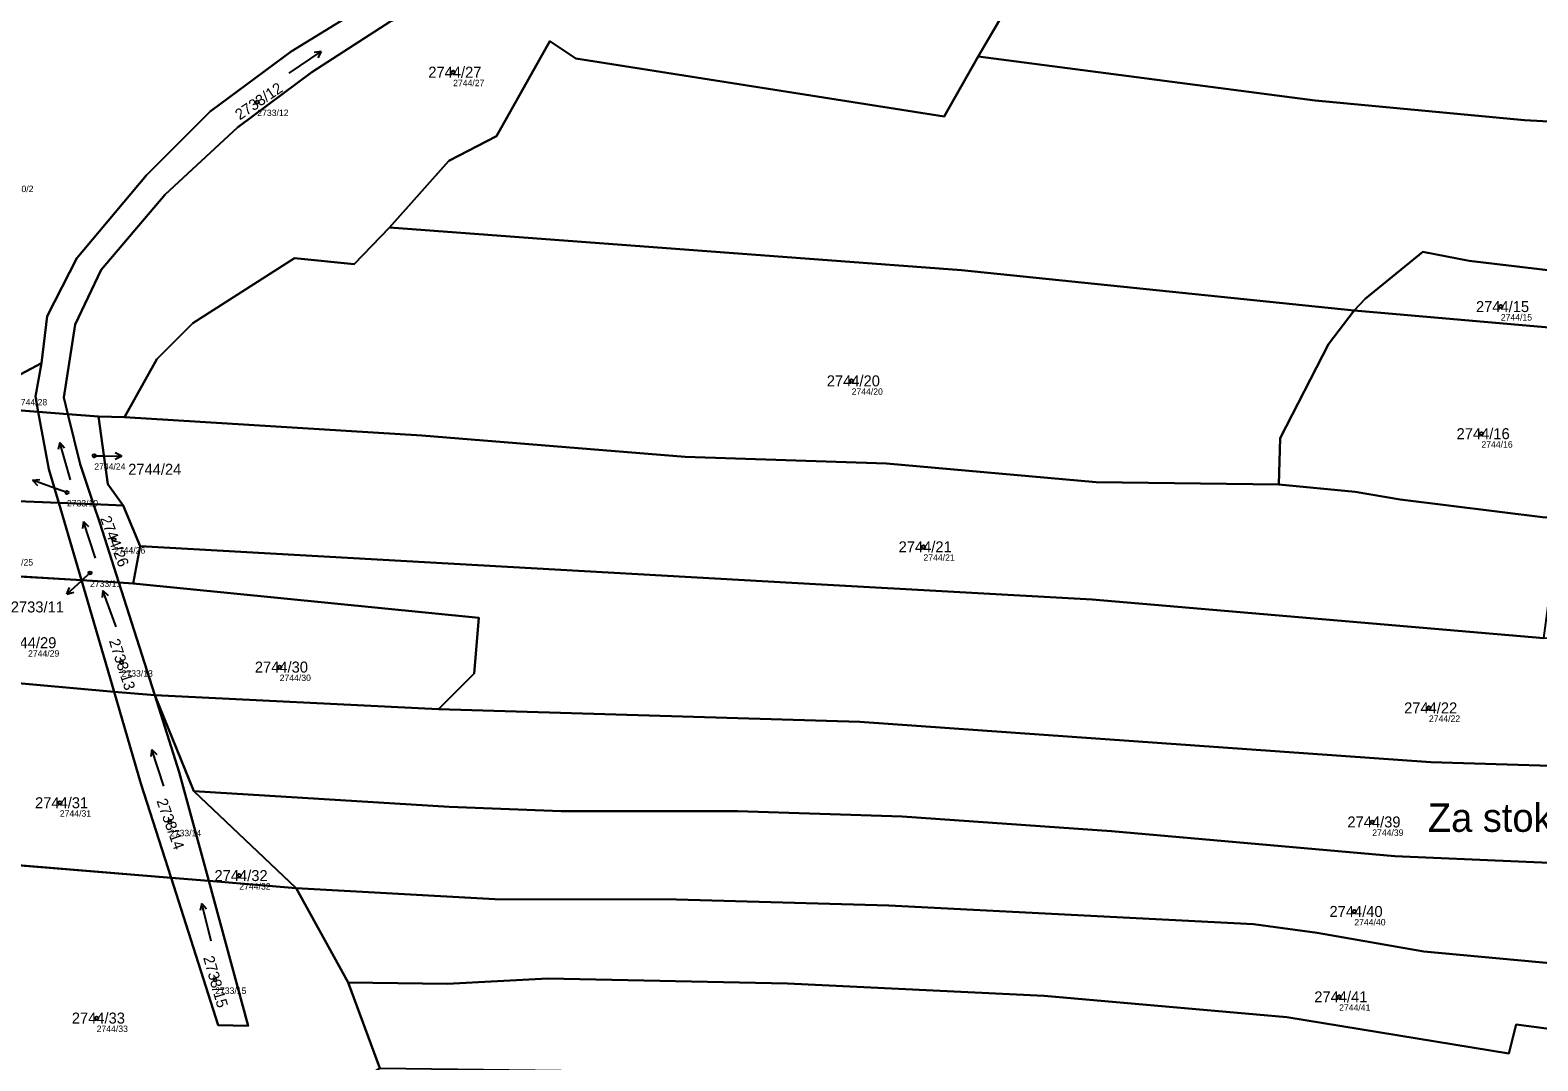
# Model space of a CAD drawing. Extents: x -739214 to -733252, y -1147612 to -1142842.
# Drawn here: x -737932.2 to -737699, y -1144633.5 to -1144474 of the extents above; entities that cross this region are included whole.
import ezdxf

# ---------------------------------------------------------------- set-up
doc = ezdxf.new("R2010")
doc.units = 0
for name, color, linetype in [('Definiční body', 7, 'Continuous'), ('Hranice parcel', 7, 'Continuous'), ('Parcelní čísla', 7, 'Continuous'), ('Polygon parcely', 7, 'Continuous'), ('Pop  PČ popisy', 7, 'Continuous'), ('Značky kultur', 7, 'Continuous')]:
    doc.layers.add(name, color=color, linetype=linetype)

msp = doc.modelspace()

# ---------------------------------------------------------------- linework, layer by layer
at = {"layer": 'Definiční body'}
for centre in [(-737866.8, -1144480.52), (-737897.09, -1144485.14), (-737704.74, -1144516.78), (-737805.16, -1144528.27), (-737707.74, -1144536.44), (-737922.31, -1144539.86), (-737926.54, -1144545.54), (-737919.25, -1144552.83), (-737794.05, -1144553.95), (-737922.97, -1144557.99), (-737918.08, -1144571.87), (-737893.63, -1144572.55), (-737715.86, -1144578.87), (-737927.63, -1144593.54), (-737910.61, -1144596.57), (-737724.63, -1144596.51), (-737899.87, -1144604.81), (-737727.4, -1144610.36), (-737903.61, -1144620.96), (-737729.75, -1144623.57), (-737921.94, -1144626.85)]:
    msp.add_circle(centre, 0.25, dxfattribs=at)
at = {"layer": 'Hranice parcel'}
for p, q in [((-737773.14, -1144456.81), (-737785.6, -1144478.09)), ((-737727.43, -1144517.4), (-737686.65, -1144520.92)), ((-737942.95, -1144532.13), (-737930.48, -1144525.51)), ((-737930.97, -1144533.06), (-737942.95, -1144532.13)), ((-737926.39, -1144533.41), (-737930.97, -1144533.06)), ((-737921.63, -1144533.78), (-737926.39, -1144533.41)), ((-737917.65, -1144533.91), (-737921.63, -1144533.78)), ((-737953.32, -1144546.12), (-737927.79, -1144547.13)), ((-737927.79, -1144547.13), (-737922.41, -1144547.35)), ((-737927.79, -1144547.13), (-737924.28, -1144559.12)), ((-737922.41, -1144547.35), (-737917.82, -1144547.53)), ((-737917.82, -1144547.53), (-737915.23, -1144553.85)), ((-737915.23, -1144553.85), (-737916.31, -1144559.61)), ((-737948.93, -1144557.6), (-737924.28, -1144559.12)), ((-737924.28, -1144559.12), (-737918.5, -1144559.48)), ((-737924.28, -1144559.12), (-737919.24, -1144576.36)), ((-737912.96, -1144576.92), (-737918.5, -1144559.48)), ((-737918.5, -1144559.48), (-737916.31, -1144559.61)), ((-737943.32, -1144574.2), (-737919.24, -1144576.36)), ((-737919.24, -1144576.36), (-737912.96, -1144576.92)), ((-737912.96, -1144576.92), (-737869.05, -1144579.05)), ((-737906.92, -1144591.77), (-737912.96, -1144576.92)), ((-737891.06, -1144606.75), (-737906.92, -1144591.77)), ((-737942.86, -1144602.48), (-737910.42, -1144605.15)), ((-737910.42, -1144605.15), (-737904.6, -1144605.63)), ((-737904.6, -1144605.63), (-737891.06, -1144606.75)), ((-737883.04, -1144621.37), (-737891.06, -1144606.75)), ((-737878.15, -1144634.59), (-737883.04, -1144621.37))]:
    msp.add_line(p, q, dxfattribs=at)
for points in [[(-737926.39, -1144533.41), (-737927.01, -1144530.86), (-737925.24, -1144519.57), (-737921.26, -1144511.11), (-737911.32, -1144499.46), (-737900.13, -1144489.08), (-737888.65, -1144480.5), (-737876.41, -1144472.62), (-737867.2, -1144468.83), (-737814.62, -1144454.1)], [(-737868.17, -1144464.26), (-737877.57, -1144468.52), (-737891.83, -1144477.32), (-737904.38, -1144486.62), (-737914.24, -1144496.47), (-737925.02, -1144509.31), (-737929.6, -1144518.25), (-737930.48, -1144525.51)], [(-737785.6, -1144478.09), (-737790.83, -1144487.35), (-737847.8, -1144478.4), (-737851.84, -1144475.71), (-737860.11, -1144490.42), (-737867.48, -1144494.24), (-737876.62, -1144504.52)], [(-737785.6, -1144478.09), (-737733.45, -1144484.87), (-737701.09, -1144487.96), (-737676.5, -1144489.26), (-737627.87, -1144492.95), (-737616.17, -1144494.42), (-737600.37, -1144496.74), (-737576.07, -1144501.23), (-737531.09, -1144511.5)], [(-737876.62, -1144504.52), (-737882.12, -1144510.23), (-737891.36, -1144509.31), (-737907.07, -1144519.34), (-737912.62, -1144524.89), (-737917.65, -1144533.91)], [(-737876.62, -1144504.52), (-737788.18, -1144511.16), (-737727.43, -1144517.4)], [(-737686.65, -1144520.92), (-737690.94, -1144511.91), (-737709.62, -1144509.71), (-737716.8, -1144508.31), (-737725.74, -1144515.57), (-737727.43, -1144517.4)], [(-737727.43, -1144517.4), (-737731.38, -1144522.61), (-737738.86, -1144537.12), (-737739.08, -1144544.3)], [(-737930.48, -1144525.51), (-737931.41, -1144530.71), (-737930.97, -1144533.06)], [(-737930.97, -1144533.06), (-737929.31, -1144541.92), (-737927.79, -1144547.13)], [(-737922.41, -1144547.35), (-737924.51, -1144541.16), (-737926.39, -1144533.41)], [(-737921.63, -1144533.78), (-737920.23, -1144544.27), (-737917.82, -1144547.53)], [(-737917.65, -1144533.91), (-737871.65, -1144536.72), (-737830.89, -1144540), (-737799.75, -1144541.03), (-737767.34, -1144543.94), (-737739.08, -1144544.3)], [(-737739.08, -1144544.3), (-737727.27, -1144545.46), (-737720.31, -1144546.63), (-737697.89, -1144549.41), (-737695, -1144549.36)], [(-737918.5, -1144559.48), (-737921.44, -1144550.22), (-737922.41, -1144547.35)], [(-737915.23, -1144553.85), (-737809.84, -1144559.77), (-737767.94, -1144562.09), (-737698.06, -1144568.08)], [(-737916.31, -1144559.61), (-737862.81, -1144564.94), (-737863.56, -1144573.56), (-737869.05, -1144579.05)], [(-737919.24, -1144576.36), (-737915.09, -1144590.56), (-737910.42, -1144605.15)], [(-737904.6, -1144605.63), (-737909.18, -1144588.8), (-737912.96, -1144576.92)], [(-737869.05, -1144579.05), (-737803.9, -1144581.02), (-737715.55, -1144587.26), (-737685.17, -1144588.21), (-737656.28, -1144590.45), (-737617.07, -1144596.37), (-737591.52, -1144603.26), (-737561.95, -1144613.5)], [(-737906.92, -1144591.77), (-737867.39, -1144594.16), (-737850.07, -1144594.84), (-737822.81, -1144594.85), (-737797.36, -1144595.68), (-737764.97, -1144597.96), (-737721.14, -1144601.78), (-737682.9, -1144603.46), (-737658.14, -1144605.97), (-737622.11, -1144611.46), (-737598.66, -1144617.19), (-737580.09, -1144623.04), (-737568.5, -1144628.61)], [(-737910.42, -1144605.15), (-737903.13, -1144627.93), (-737898.51, -1144628.03), (-737904.6, -1144605.63)], [(-737891.06, -1144606.75), (-737860.35, -1144608.46), (-737832.24, -1144608.5), (-737799.41, -1144609.43), (-737743.02, -1144612.33), (-737733.13, -1144613.67), (-737716.64, -1144616.57), (-737696.03, -1144618.45), (-737694.77, -1144614.8), (-737657.82, -1144619.67), (-737629.39, -1144624.64), (-737616.03, -1144627.71), (-737585.66, -1144636.92), (-737573.23, -1144641.35)], [(-737883.04, -1144621.37), (-737867.73, -1144621.57), (-737852.15, -1144620.71), (-737815.08, -1144621.5), (-737775.39, -1144623.43), (-737737.84, -1144626.71), (-737703.5, -1144632.35), (-737702.39, -1144627.85), (-737672.66, -1144631.78), (-737651.8, -1144635.91), (-737632.6, -1144639.06), (-737609.23, -1144646.15), (-737582.22, -1144655.83)]]:
    msp.add_lwpolyline(points, dxfattribs=at)
at = {"layer": 'Polygon parcely'}
for points in [[(-737676.5, -1144489.26), (-737627.87, -1144492.95), (-737616.17, -1144494.42), (-737600.37, -1144496.74), (-737576.07, -1144501.23), (-737531.09, -1144511.5), (-737529.44, -1144511.78), (-737526.15, -1144491.59), (-737527.8, -1144458.01), (-737551.39, -1144455.57), (-737569.83, -1144452.11), (-737583.62, -1144450.77), (-737650.15, -1144446.91), (-737705.41, -1144442.38), (-737711.09, -1144441.92), (-737719.38, -1144441.24), (-737747.06, -1144439.73), (-737762.92, -1144440.22), (-737769.4, -1144441.94), (-737768.36, -1144448.37), (-737773.14, -1144456.81), (-737785.6, -1144478.09), (-737733.45, -1144484.87), (-737701.09, -1144487.96)], [(-737931.41, -1144530.71), (-737930.97, -1144533.06), (-737926.39, -1144533.41), (-737927.01, -1144530.86), (-737925.24, -1144519.57), (-737921.26, -1144511.11), (-737911.32, -1144499.46), (-737900.13, -1144489.08), (-737888.65, -1144480.5), (-737876.41, -1144472.62), (-737867.2, -1144468.83), (-737814.62, -1144454.1), (-737835.54, -1144454.6), (-737868.17, -1144464.26), (-737877.57, -1144468.52), (-737891.83, -1144477.32), (-737904.38, -1144486.62), (-737914.24, -1144496.47), (-737925.02, -1144509.31), (-737929.6, -1144518.25), (-737930.48, -1144525.51)], [(-737955.11, -1144459.11), (-737955.01, -1144470.75), (-737954.9, -1144484.25), (-737955.35, -1144491.07), (-737956.06, -1144501.75), (-737958.01, -1144530.96), (-737942.95, -1144532.13), (-737930.48, -1144525.51), (-737929.6, -1144518.25), (-737925.02, -1144509.31), (-737914.24, -1144496.47), (-737904.38, -1144486.62), (-737891.83, -1144477.32), (-737877.57, -1144468.52), (-737868.17, -1144464.26), (-737934.96, -1144460.74)], [(-737830.89, -1144540), (-737799.75, -1144541.03), (-737767.34, -1144543.94), (-737739.08, -1144544.3), (-737738.86, -1144537.12), (-737731.38, -1144522.61), (-737727.43, -1144517.4), (-737788.18, -1144511.16), (-737876.62, -1144504.52), (-737882.12, -1144510.23), (-737891.36, -1144509.31), (-737907.07, -1144519.34), (-737912.62, -1144524.89), (-737917.65, -1144533.91), (-737871.65, -1144536.72)], [(-737716.8, -1144508.31), (-737725.74, -1144515.57), (-737727.43, -1144517.4), (-737686.65, -1144520.92), (-737690.94, -1144511.91), (-737709.62, -1144509.71)], [(-737738.86, -1144537.12), (-737739.08, -1144544.3), (-737727.27, -1144545.46), (-737720.31, -1144546.63), (-737697.89, -1144549.41), (-737695, -1144549.36), (-737672.64, -1144549.91), (-737686.65, -1144520.92), (-737727.43, -1144517.4), (-737731.38, -1144522.61)], [(-737930.97, -1144533.06), (-737931.41, -1144530.71), (-737930.48, -1144525.51), (-737942.95, -1144532.13)], [(-737930.97, -1144533.06), (-737942.95, -1144532.13), (-737956.02, -1144539.07), (-737953.32, -1144546.12), (-737927.79, -1144547.13), (-737929.31, -1144541.92)], [(-737927.79, -1144547.13), (-737922.41, -1144547.35), (-737924.51, -1144541.16), (-737926.39, -1144533.41), (-737930.97, -1144533.06), (-737929.31, -1144541.92)], [(-737917.82, -1144547.53), (-737920.23, -1144544.27), (-737921.63, -1144533.78), (-737926.39, -1144533.41), (-737924.51, -1144541.16), (-737922.41, -1144547.35)], [(-737920.23, -1144544.27), (-737917.82, -1144547.53), (-737915.23, -1144553.85), (-737809.84, -1144559.77), (-737767.94, -1144562.09), (-737698.06, -1144568.08), (-737697.18, -1144561.12), (-737695, -1144549.36), (-737697.89, -1144549.41), (-737720.31, -1144546.63), (-737727.27, -1144545.46), (-737739.08, -1144544.3), (-737767.34, -1144543.94), (-737799.75, -1144541.03), (-737830.89, -1144540), (-737871.65, -1144536.72), (-737917.65, -1144533.91), (-737921.63, -1144533.78)], [(-737948.93, -1144557.6), (-737924.28, -1144559.12), (-737927.79, -1144547.13), (-737953.32, -1144546.12)], [(-737918.5, -1144559.48), (-737921.44, -1144550.22), (-737922.41, -1144547.35), (-737927.79, -1144547.13), (-737924.28, -1144559.12)], [(-737916.31, -1144559.61), (-737915.23, -1144553.85), (-737917.82, -1144547.53), (-737922.41, -1144547.35), (-737921.44, -1144550.22), (-737918.5, -1144559.48)], [(-737656.28, -1144590.45), (-737617.07, -1144596.37), (-737591.52, -1144603.26), (-737561.95, -1144613.5), (-737555.62, -1144598.88), (-737581.61, -1144590.43), (-737616.17, -1144581.32), (-737646.17, -1144576.7), (-737670.78, -1144574.07), (-737677.25, -1144574.53), (-737692.27, -1144572.92), (-737694.4, -1144568.38), (-737698.06, -1144568.08), (-737767.94, -1144562.09), (-737809.84, -1144559.77), (-737915.23, -1144553.85), (-737916.31, -1144559.61), (-737862.81, -1144564.94), (-737863.56, -1144573.56), (-737869.05, -1144579.05), (-737803.9, -1144581.02), (-737715.55, -1144587.26), (-737685.17, -1144588.21)], [(-737944.37, -1144569.52), (-737943.32, -1144574.2), (-737919.24, -1144576.36), (-737924.28, -1144559.12), (-737948.93, -1144557.6)], [(-737912.96, -1144576.92), (-737918.5, -1144559.48), (-737924.28, -1144559.12), (-737919.24, -1144576.36)], [(-737869.05, -1144579.05), (-737863.56, -1144573.56), (-737862.81, -1144564.94), (-737916.31, -1144559.61), (-737918.5, -1144559.48), (-737912.96, -1144576.92)], [(-737910.42, -1144605.15), (-737915.09, -1144590.56), (-737919.24, -1144576.36), (-737943.32, -1144574.2), (-737940.96, -1144584.68), (-737942.86, -1144602.48)], [(-737904.6, -1144605.63), (-737909.18, -1144588.8), (-737912.96, -1144576.92), (-737919.24, -1144576.36), (-737915.09, -1144590.56), (-737910.42, -1144605.15)], [(-737891.06, -1144606.75), (-737906.92, -1144591.77), (-737912.96, -1144576.92), (-737909.18, -1144588.8), (-737904.6, -1144605.63)], [(-737598.66, -1144617.19), (-737580.09, -1144623.04), (-737568.5, -1144628.61), (-737561.95, -1144613.5), (-737591.52, -1144603.26), (-737617.07, -1144596.37), (-737656.28, -1144590.45), (-737685.17, -1144588.21), (-737715.55, -1144587.26), (-737803.9, -1144581.02), (-737869.05, -1144579.05), (-737912.96, -1144576.92), (-737906.92, -1144591.77), (-737867.39, -1144594.16), (-737850.07, -1144594.84), (-737822.81, -1144594.85), (-737797.36, -1144595.68), (-737764.97, -1144597.96), (-737721.14, -1144601.78), (-737682.9, -1144603.46), (-737658.14, -1144605.97), (-737622.11, -1144611.46)], [(-737883.04, -1144621.37), (-737891.06, -1144606.75), (-737904.6, -1144605.63), (-737898.51, -1144628.03), (-737903.13, -1144627.93), (-737910.42, -1144605.15), (-737942.86, -1144602.48), (-737947.13, -1144642.41), (-737936.59, -1144643.76), (-737914.72, -1144642.53), (-737901.54, -1144642.73), (-737892.69, -1144643.45), (-737878.15, -1144634.59)], [(-737910.42, -1144605.15), (-737903.13, -1144627.93), (-737898.51, -1144628.03), (-737904.6, -1144605.63)], [(-737637.35, -1144649.22), (-737604.53, -1144659.49), (-737591.13, -1144664.67), (-737582.22, -1144655.83), (-737609.23, -1144646.15), (-737632.6, -1144639.06), (-737651.8, -1144635.91), (-737672.66, -1144631.78), (-737702.39, -1144627.85), (-737703.5, -1144632.35), (-737737.84, -1144626.71), (-737775.39, -1144623.43), (-737815.08, -1144621.5), (-737852.15, -1144620.71), (-737867.73, -1144621.57), (-737883.04, -1144621.37), (-737878.15, -1144634.59), (-737806.05, -1144635.53), (-737772.78, -1144637.39), (-737734.45, -1144641.63), (-737704.83, -1144645.91), (-737703.81, -1144636.4), (-737667.6, -1144642.51)]]:
    msp.add_lwpolyline(points, close=True, dxfattribs=at)
for points in [[(-737876.41, -1144472.62), (-737888.65, -1144480.5), (-737900.13, -1144489.08), (-737911.32, -1144499.46), (-737921.26, -1144511.11), (-737925.24, -1144519.57), (-737927.01, -1144530.86), (-737926.39, -1144533.41), (-737921.63, -1144533.78), (-737917.65, -1144533.91), (-737912.62, -1144524.89), (-737907.07, -1144519.34), (-737891.36, -1144509.31), (-737882.12, -1144510.23), (-737876.62, -1144504.52), (-737867.48, -1144494.24), (-737860.11, -1144490.42), (-737851.84, -1144475.71), (-737847.8, -1144478.4), (-737790.83, -1144487.35), (-737785.6, -1144478.09), (-737773.14, -1144456.81)], [(-737676.5, -1144489.26), (-737701.09, -1144487.96), (-737733.45, -1144484.87), (-737785.6, -1144478.09), (-737790.83, -1144487.35), (-737847.8, -1144478.4), (-737851.84, -1144475.71), (-737860.11, -1144490.42), (-737867.48, -1144494.24), (-737876.62, -1144504.52), (-737788.18, -1144511.16), (-737727.43, -1144517.4), (-737725.74, -1144515.57), (-737716.8, -1144508.31), (-737709.62, -1144509.71), (-737690.94, -1144511.91)], [(-737682.9, -1144603.46), (-737721.14, -1144601.78), (-737764.97, -1144597.96), (-737797.36, -1144595.68), (-737822.81, -1144594.85), (-737850.07, -1144594.84), (-737867.39, -1144594.16), (-737906.92, -1144591.77), (-737891.06, -1144606.75), (-737860.35, -1144608.46), (-737832.24, -1144608.5), (-737799.41, -1144609.43), (-737743.02, -1144612.33), (-737733.13, -1144613.67), (-737716.64, -1144616.57), (-737696.03, -1144618.45)], [(-737696.03, -1144618.45), (-737716.64, -1144616.57), (-737733.13, -1144613.67), (-737743.02, -1144612.33), (-737799.41, -1144609.43), (-737832.24, -1144608.5), (-737860.35, -1144608.46), (-737891.06, -1144606.75), (-737883.04, -1144621.37), (-737867.73, -1144621.57), (-737852.15, -1144620.71), (-737815.08, -1144621.5), (-737775.39, -1144623.43), (-737737.84, -1144626.71), (-737703.5, -1144632.35), (-737702.39, -1144627.85), (-737672.66, -1144631.78)]]:
    msp.add_lwpolyline(points, dxfattribs=at)
at = {"layer": 'Pop  PČ popisy'}
for p, q in [((-737922.31, -1144539.86), (-737921.06, -1144539.89)), ((-737921.06, -1144539.89), (-737918.06, -1144539.94)), ((-737918.06, -1144539.94), (-737919.07, -1144540.43)), ((-737918.06, -1144539.94), (-737919.05, -1144539.42)), ((-737931.84, -1144543.63), (-737930.73, -1144543.51)), ((-737929.02, -1144544.66), (-737931.84, -1144543.63)), ((-737931.84, -1144543.63), (-737931.07, -1144544.45)), ((-737926.54, -1144545.54), (-737929.02, -1144544.66)), ((-737924.33, -1144559.24), (-737926.53, -1144561.29)), ((-737922.97, -1144557.99), (-737924.33, -1144559.24)), ((-737926.53, -1144561.29), (-737926.13, -1144560.24)), ((-737926.53, -1144561.29), (-737925.45, -1144560.97))]:
    msp.add_line(p, q, dxfattribs=at)
at = {"layer": 'Značky kultur'}
for p, q in [((-737892.18, -1144480.69), (-737887.2, -1144477.33)), ((-737887.2, -1144477.33), (-737888.29, -1144477.46)), ((-737887.2, -1144477.33), (-737887.73, -1144478.29)), ((-737927.65, -1144537.82), (-737927.87, -1144538.9)), ((-737926, -1144543.58), (-737927.65, -1144537.82)), ((-737927.65, -1144537.82), (-737926.9, -1144538.62)), ((-737923.97, -1144550.01), (-737924.15, -1144551.09)), ((-737922.12, -1144555.71), (-737923.97, -1144550.01)), ((-737923.97, -1144550.01), (-737923.2, -1144550.78)), ((-737920.97, -1144560.7), (-737921.11, -1144561.79)), ((-737918.92, -1144566.34), (-737920.97, -1144560.7)), ((-737920.97, -1144560.7), (-737920.17, -1144561.45)), ((-737913.39, -1144585.29), (-737913.57, -1144586.37)), ((-737911.54, -1144590.99), (-737913.39, -1144585.29)), ((-737913.39, -1144585.29), (-737912.61, -1144586.06)), ((-737905.69, -1144609.12), (-737905.94, -1144610.19)), ((-737904.24, -1144614.94), (-737905.69, -1144609.12)), ((-737905.69, -1144609.12), (-737904.97, -1144609.95))]:
    msp.add_line(p, q, dxfattribs=at)

# ---------------------------------------------------------------- texts
at = {"layer": 'Definiční body'}
for s, p in [('2744/27', (-737866.8, -1144482.68)), ('2733/12', (-737897.09, -1144487.3)), ('2740/2', (-737935.8, -1144499.07)), ('2744/15', (-737704.74, -1144518.94)), ('2744/28', (-737934.42, -1144532.07)), ('2744/20', (-737805.16, -1144530.43)), ('2744/16', (-737707.74, -1144538.6)), ('2744/24', (-737922.31, -1144542.02)), ('2733/10', (-737926.54, -1144547.7)), ('2744/26', (-737919.25, -1144554.99)), ('2744/25', (-737936.6, -1144556.84)), ('2744/21', (-737794.05, -1144556.11)), ('2733/11', (-737922.97, -1144560.15)), ('2744/29', (-737932.55, -1144570.94)), ('2733/13', (-737918.08, -1144574.03)), ('2744/30', (-737893.63, -1144574.71)), ('2744/22', (-737715.86, -1144581.03)), ('2744/31', (-737927.63, -1144595.7)), ('2733/14', (-737910.61, -1144598.73)), ('2744/39', (-737724.63, -1144598.67)), ('2744/32', (-737899.87, -1144606.97)), ('2744/40', (-737727.4, -1144612.52)), ('2733/15', (-737903.61, -1144623.12)), ('2744/41', (-737729.75, -1144625.73)), ('2744/33', (-737921.94, -1144629.01))]:
    msp.add_text(s, height=1, dxfattribs=at).set_placement(p)
at = {"layer": 'Parcelní čísla'}
for s, p in [('2744/27', (-737870.64, -1144481.37)), ('2744/15', (-737708.58, -1144517.63)), ('2744/20', (-737809, -1144529.12)), ('2744/16', (-737711.58, -1144537.29)), ('2744/24', (-737917.06, -1144542.8)), ('2744/21', (-737797.89, -1144554.8)), ('2733/11', (-737935.22, -1144564.1)), ('2744/29', (-737936.39, -1144569.63)), ('2744/30', (-737897.47, -1144573.4)), ('2744/22', (-737719.7, -1144579.72)), ('2744/31', (-737931.47, -1144594.39)), ('2744/39', (-737728.47, -1144597.36)), ('2744/32', (-737903.71, -1144605.66)), ('2744/40', (-737731.24, -1144611.21)), ('2744/41', (-737733.59, -1144624.42)), ('2744/33', (-737925.78, -1144627.7))]:
    msp.add_text(s, height=1.7, dxfattribs=at).set_placement(p)
for s, rotation, p in [('2733/12', 34, (-737899.8, -1144487.99)), ('2744/26', 291, (-737921.42, -1144549.55)), ('2733/13', 288, (-737920.07, -1144568.48)), ('2733/14', 290, (-737912.72, -1144593.25)), ('2733/15', 286, (-737905.48, -1144617.5))]:
    msp.add_text(s, height=1.7, rotation=rotation, dxfattribs=at).set_placement(p)
at = {"layer": 'Pop  PČ popisy'}
msp.add_text('Za stokou', height=4.4, dxfattribs=at).set_placement((-737716.02, -1144598.04))

doc.saveas('drawing.dxf')
